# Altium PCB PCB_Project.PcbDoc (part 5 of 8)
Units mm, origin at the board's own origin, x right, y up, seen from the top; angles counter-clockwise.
Board outline 250 x 200 mm, 6 copper layers (Top Shielding/Sig, Sig 1, PWR, GND, Sig 4, Bottom Shielding/Sig), stack 1.568 mm thick; 736 components, 420 nets, 1929 pads, 2185 vias.
Unrouted connection lines stored in the file: 47.
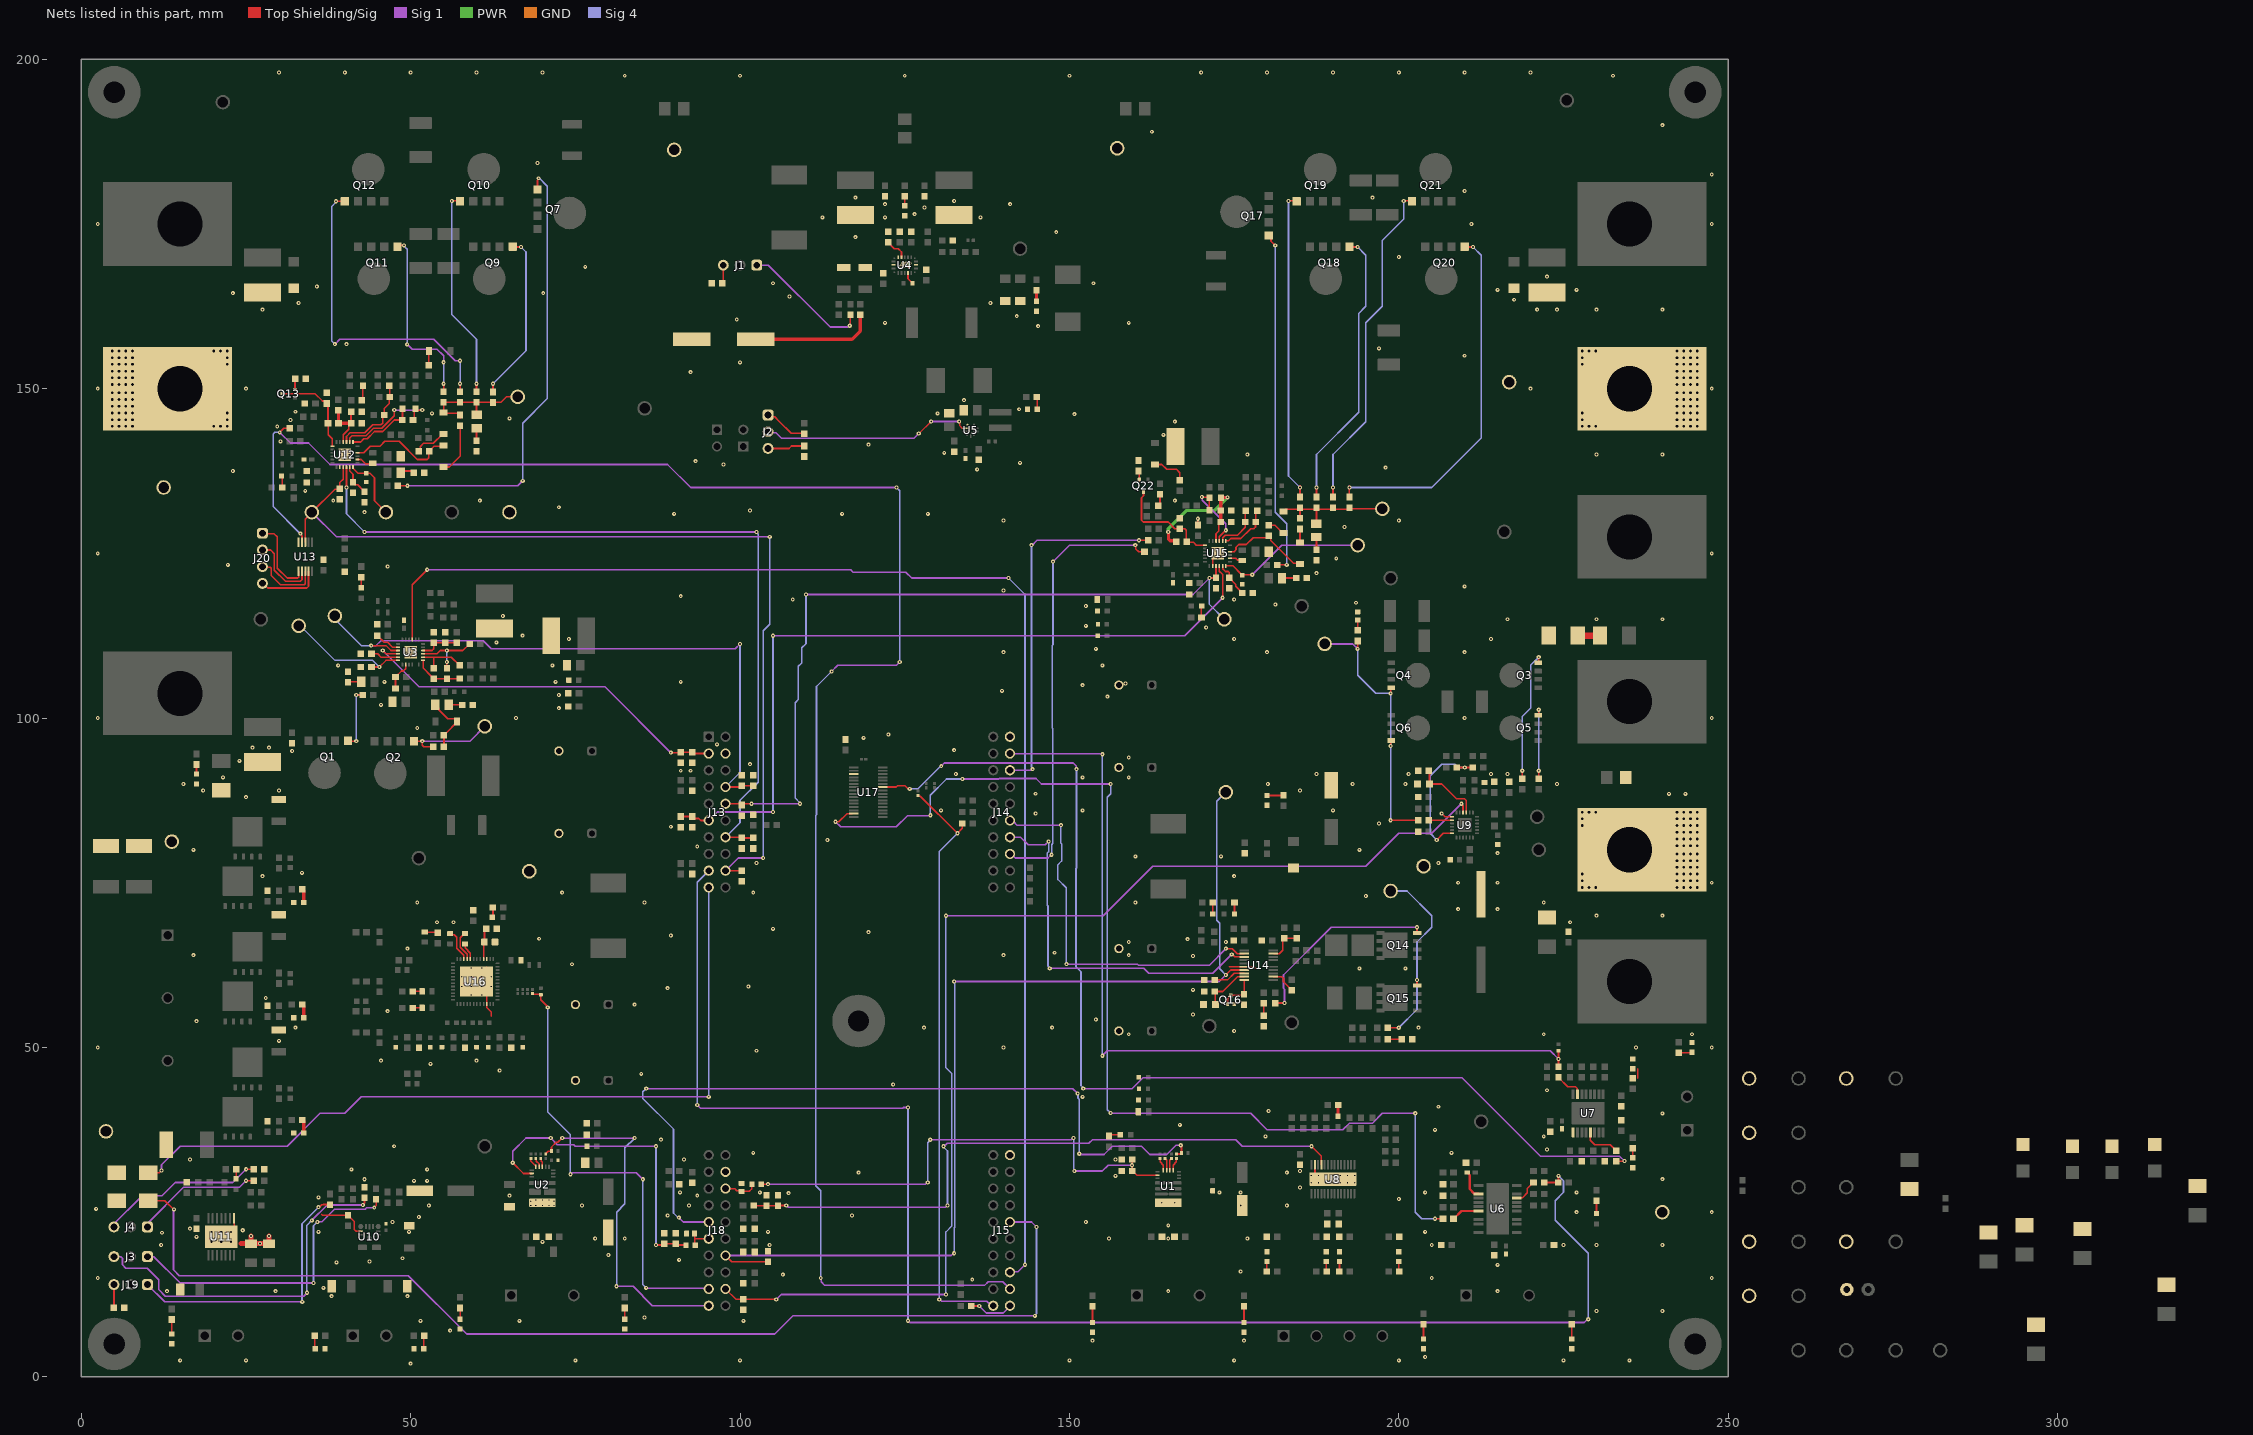
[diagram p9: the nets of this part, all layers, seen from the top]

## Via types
v1: diameter 0.635, hole 0.254, Top Shielding/Sig to Bottom Shielding/Sig, tented both sides, 778 vias
v2: diameter 0.6, hole 0.254, Top Shielding/Sig to Bottom Shielding/Sig, tented both sides, 726 vias
v3: diameter 0.813, hole 0.406, Top Shielding/Sig to Bottom Shielding/Sig, 522 vias
v4: diameter 0.5, hole 0.2, Top Shielding/Sig to Bottom Shielding/Sig, tented both sides, 95 vias
v5: diameter 0.5, hole 0.2, Top Shielding/Sig to Bottom Shielding/Sig, 39 vias
v6: diameter 0.635, hole 0.254, Top Shielding/Sig to Bottom Shielding/Sig, 10 vias
v7: diameter 0.63, hole 0.33, Top Shielding/Sig to Bottom Shielding/Sig, tented both sides, 6 vias
v8: diameter 0.75, hole 0.254, Top Shielding/Sig to Bottom Shielding/Sig, tented both sides, 6 vias
v9: diameter 0.5, hole 0.2, Top Shielding/Sig to Bottom Shielding/Sig, tented top, 3 vias

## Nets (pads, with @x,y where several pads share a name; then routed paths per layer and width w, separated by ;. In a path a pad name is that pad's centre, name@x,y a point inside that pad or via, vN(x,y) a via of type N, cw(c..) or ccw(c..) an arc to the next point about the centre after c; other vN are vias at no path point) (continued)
GND: C1.1 C2.1 C3.1 C4.1 C5.1 C6.2 C7.1 C8.1 C9.1 C10.1 C11.2 C12.2 C13.2 C14.2 C15.1 C16.1 C17.1 C18.1 C19.2 C20.2 C21.1 C23.2 C24.1 C25.2 C26.1 C27.1 C28.2 C29.2 C30.2 C31.2 C32.1 C33.1 C34.1 C35.2 C36.2 C37.1 C38.1 C40.1 C41.2 C42.2 C43.2 C44.2 C45.2 C46.2 C47.2 C49.1 C51.2 C54.2 C55.2 C56.2 C57.2 C58.2 C60.1 C61.1 C62.1 C63.1 C64.2 C65.2 C66.2 C67.2 C69.2 C70.2 C71.2 C72.2 C73.2 C74.2 C75.2 C76.2 C77.2 C78.2 C79.2 C80.2 C81.2 C82.2 C83.2 C84.2 C85.2 C86.2 C87.2 C88.2 C89.2 C90.2 C91.2 C92.2 C94.1 C95.2 C96.2 C97.1 C99.1 C100.1 C102.2 C103.2 C104.2 C105.2 C106.2 C107.2 C108.2 C109.2 C110.2 C111.2 C112.2 C114.1 C115.2 C116.1 C117.2 C118.2 C119.2 C120.2 C122.2 C123.2 C125.2 C127.2 C128.2 C129.1 C130.2 C131.2 C132.2 C133.2 C134.1 C135.2 C136.2 C137.1 C138.1 C140.2 C142.2 C144.1 C145.2 C146.2 C147.1 C148.2 C150.2 C151.2 C152.2 C153.2 C155.2 C157.2 C158.1 C159.2 C160.2 C161.2 C162.2 C163.1 C164.2 C167.2 C168.2 C170.2 C174.2 C178.2 C180.2 C185.2 C186.2 C187.2 C188.2 C189.1 C190.1 C191.1 C192.1 C196.1 C197.1 C198.1 C199.2 D1.2 D2.2 D4.2 D5.2 D6.2 D7.2 D11.2 D13.2 D15.2 D16.2 D17.2 D18.2 D20.2 D21.2 D22.2 D23.2 D26.1 D27.2 D29.2 D30.2 D31.2 D34.1 D35.2 D38.2 D39.1 D40.2 D44.1 D47.2 D48.2 D49.2 D55.2 D56.2 D57.2 D58.2 D59.2 D60.2 D61.2 D62.2 D63.2 D64.2 D65.2 J13.22 J14.20 J15.60 J18.62 Q16.2 R8.1 R14.1 R42.1 R43.1 R44.1 R45.1 R51.1 R54.1 R55.1 R56.1 R59.1 R60.1 R62.1 R73.1 R75.2 R81.2 R85.1 R102.1 R103.1 R119.1 R121.1 R126.1 R127.1 R128.2 R135.1 R137.1 R141.1 R145.1 R151.1 R152.1 R175.2 R188.1 R189.1 R190.1 R203.1 R207.2 R209.1 R211.1 R212.1 R236.2 R249.1 R250.1 R251.1 R252.1 R284.1 R285.1 R286.1 R287.2 R288.2 R289.2 R299.1 R303.1 R304.1 S1.1 S2.2 T5.1 T7.1 TP29.1 TP30.1 TP31.1 TP32.1 TP33.1 TP34.1 TP35.1 TP36.1 TP37.1 TP38.1 U1.7 U2.6 U3.8 U3.25 U4.6 U4.9 U4.19 U4.21 U5.4 U6.2 U7.1 U8.13 U8.29 U9.13 U10.11 U11.1 U11.15 U12.8 U12.25 U13.5 U14.6 U15.8 U15.25 U16.10 U16.27 U16.49 U17.3 | length 55
  Top Shielding/Sig w0.25: U11.15@21.25,21.25 21.625,21.25 23.2,22.825 U11.1@23.2,24.05 ; 36.5,24.65 36.6,24.55 38.75,24.55 R137.1@40.5,24.55 40.5,24.525 41.45,23.575 41.45,22.375 41.75,22.075 U10.11@42.4,22.075 ; C58.2@44.95,112.5 44.975,112.5 45.975,111.5 46.5,111.5 47.25,110.75 U3.8@48.1,110.75 ; U16.49@60,60 61.562,58.438 U16.10@61.562,56.6 61.562,56.063 62.25,55.375 62.25,54.75 ; v4(60.786,62.05) 61.437,62.05 U16.49@61.562,62.175 ; C147.1@169.5,129.3 v1(169.5,130.25) ; U15.8@171.75,123.1 171.75,124.95 v4(171.8,125) ; 174.25,62.25 U14.6@176.55,62.25 178,62.25 178.25,62 ; U8.13@187.25,32.2 187.266,32.184 187.266,30.875 188.141,30 U8.29@190,30 ; v1(206.5,85.5) 207,85 U9.13@208.1,85
  Top Shielding/Sig w0.35: C73.2@210.4,31 210.5,31 210.625,30.875 210.625,30.775 210.75,30.65 210.75,28.5 211.425,27.825 212.05,27.825 U6.2@212.1,27.775
  Top Shielding/Sig w0.75: 24.25,20.25 25.7,20.25 C109.2@25.75,20.2 ; v1(25.75,21.375) C109.2@25.75,20.2 ; v1(28.5,21.375) C110.2@28.5,20.2 28.45,20.25 v1(27.125,20.25) 25.8,20.25 C109.2@25.75,20.2
  GND w0.35: v3(7.761,152.667) 12.083,152.667 14.75,150 T5.1@15,150
  other v1: 24.5,22.25 43,30
  other v2: 50,2 15,2.5 25,2.5 75,2.5 100,2.5 150,2.5 175,2.5 200,2.5 225,2.5 235,2.5 204,3 153.5,5.5 176.5,5.5 56,7 51.5,8.5 66.5,8.5 100.5,8.5 85.5,9 230,10 240,10 38,12.25 49.5,12.25 13,13 29.5,13 165,13 215,13 36.75,13.5 135.25,14.75 2.5,15 205,15 247.5,15 106.5,15.5 176,16 215,17 38.75,17.375 43.75,17.5 90.75,17.75 48.75,18 80,18.5 12.125,20 104.5,20 205,20 225,20 230,20 240,20 70,20.5 78,21 82.5,21 156,21 165,21 177,21 17.5,21.25 12.254,21.871 36,22 49.75,22 104.25,22 204,22 16.5,22.5 165,23 47.25,23.5 152.5,23.5 51.25,24.25 89,24.5 117,24.5 227,25 247.5,25 2.25,25.5 52.75,26 76,26 92.25,26 176,26 183,26 200,27 36,27.25 65,27.5 93.5,27.5 107.375,27.875 90.875,28 103,28 172.75,28 176,28 204,28 227,28 185,28.75 50.5,29.75 52.5,29.75 240,30 157,30.5 118,31 183,31 185,31.25 41,31.5 52.5,31.5 16.5,33 91.5,33 157,33 102,34 208,34 222.5,34.5 47.5,35 88,36 179.75,36.5 222,36.5 205.5,37.5 166.75,38.25 240,40 180.25,40.362 206,41 152,42.5 222.5,43.5 123.25,44.375 85,46 63.5,46.5 53,47.5 45.5,48 60,48 102.5,49.5 2.5,50 140,50 236,50 247.5,50 30,51 159,52 222,52 244.5,52 175,52.5 32.5,53 127.923,53 147.375,53 203,53 17.5,54 154,54.25 168.75,55 46.5,55.5 84,56.5 28,57.5 168.75,58.75 89,59 101.25,59.25 194,62 201,62 74.5,62.625 168.75,63.875 17,64 140,64 159,64 147.75,64.375 49.5,65 159,66 173.75,66 167.942,66.442 69.5,66.5 89.5,67 119.5,67.5 105,68 54,69 56.5,69 226,69 230,70 240,70 209,71 215,71 51,72 85.5,72 160,72 222,72 195,73 73,73.5 102,73.5 209,75 215,75 247.5,75 27.5,76 175,76 33.5,76.5 102.5,78 206,78 160,79 173,79 215,79.5 17,80 194,80 93.5,80.5 113.25,81.5 89.5,83.5 197,84 144.875,85.5 130.5,86 152,86 190,86 25,88 144.875,88.509 18.5,89 30,89 185,89 15.5,90 180.125,90 193,90 201,90 224,90 21.5,91 152,91 159,91 132.75,91.5 187.5,91.5 201.5,91.5 214,91.5 216.5,91.5 91,92 92.5,92 101.5,93 24,93.5 159,94 32,95 132.5,95.125 26,95.5 28.5,95.5 96.5,96 118.766,96.996 122.5,97.5 51,98.5 2.5,100 66,100 210,100 247.5,100 72.5,101.5 45.5,102 155.75,103.25 72.5,103.5 139.75,104.125 152,105 158.5,105.25 46,105.5 72,105.5 91,105.5 39,108 71.5,108 155,108 140,110 180,110 210,110 154,110.5 63,111.5 74,112 175,112 214,112 67,112.5 170.75,113.75 152.5,114 216.5,115 230,115 240,115 64,115.5 152.5,117 181.25,117.25 193.5,117.5 108,118 175,118 91,118.5 140,119.375 210,120 187.5,122 46.5,123 22.25,123.25 190.5,124.25 2.5,125 247.5,125 191.75,129 140,130 200,130 90,131 115.5,131 128.5,131 43,131.25 101.5,131.5 72.5,132 38.25,133 60.5,133 166,133 34,134.5 23,137.5 136,137.75 198,138 97.5,138.5 142.5,138.75 93.25,139 177,140 230,140 240,140 131,140.25 119.5,141.5 30.25,142 164.25,143 29.75,144.25 166,145 31.75,145.25 65,145.5 150.75,146.125 53.25,146.25 130,146.25 32.5,146.5 142.375,146.875 134,148.25 2.5,150 25,150 220,150 247.5,150 92.5,152.5 100,154 210,155 197,156.125 40.25,156.75 145.25,159.5 122,160 159,160 99.5,160.5 142,161 27.5,162 221,162 224,162 230,162 240,162 33,163 138,163 217.5,163.5 107.5,164 23,164.5 70.125,164.5 215,165 227,165 35.75,165.5 105,166 153.625,166 222.5,167 76.5,168.5 200,170 117.5,173 148,173.75 2.5,175 211,175 247.5,175 112.5,176 122,176 136.5,176 126.5,176.5 128,177.5 122,178 141,178 132.5,178.5 117.5,179 196,179 210,180 247.5,182.5 69.25,184.25 162.5,189 240,190 82.5,197.5 100,197.5 125,197.5 150,197.5 232.5,197.5 30,198 40,198 50,198 60,198 70,198 170,198 180,198 190,198 200,198 210,198 220,198
  other v3: 4.713,144.285 5.729,144.285 6.745,144.285 7.761,144.285 20.112,144.285 21.128,144.285 22.144,144.285 227.856,144.285 228.872,144.285 229.888,144.285 242.239,144.285 243.255,144.285 244.271,144.285 245.287,144.285 4.713,145.301 5.729,145.301 6.745,145.301 7.761,145.301 22.144,145.301 227.856,145.301 242.239,145.301 243.255,145.301 244.271,145.301 245.287,145.301 4.713,146.317 5.729,146.317 6.745,146.317 7.761,146.317 22.144,146.317 227.856,146.317 242.239,146.317 243.255,146.317 244.271,146.317 245.287,146.317 4.713,147.333 5.729,147.333 6.745,147.333 7.761,147.333 242.239,147.333 243.255,147.333 244.271,147.333 245.287,147.333 4.713,148.349 5.729,148.349 6.745,148.349 7.761,148.349 242.239,148.349 243.255,148.349 244.271,148.349 245.287,148.349 4.713,149.365 5.729,149.365 6.745,149.365 7.761,149.365 242.239,149.365 243.255,149.365 244.271,149.365 245.287,149.365 4.713,150.635 5.729,150.635 6.745,150.635 7.761,150.635 242.239,150.635 243.255,150.635 244.271,150.635 245.287,150.635 4.713,151.651 5.729,151.651 6.745,151.651 7.761,151.651 242.239,151.651 243.255,151.651 244.271,151.651 245.287,151.651 4.713,152.667 5.729,152.667 6.745,152.667 242.239,152.667 243.255,152.667 244.271,152.667 245.287,152.667 4.713,153.683 5.729,153.683 6.745,153.683 7.761,153.683 22.144,153.683 227.856,153.683 242.239,153.683 243.255,153.683 244.271,153.683 245.287,153.683 4.713,154.699 5.729,154.699 6.745,154.699 7.761,154.699 22.144,154.699 227.856,154.699 242.239,154.699 243.255,154.699 244.271,154.699 245.287,154.699 4.713,155.715 5.729,155.715 6.745,155.715 7.761,155.715 20.112,155.715 21.128,155.715 22.144,155.715 227.856,155.715 228.872,155.715 229.888,155.715 242.239,155.715 243.255,155.715 244.271,155.715 245.287,155.715
  other v4: 68.25,26 69,26 70,26 71,26 71.75,26 68.25,26.65 71.75,26.65 69,26.85 70,26.85 71,26.85 186.7,29.45 187.8,29.45 188.9,29.45 190,29.45 191.1,29.45 192.2,29.45 193.3,29.45 186.7,30.55 187.8,30.55 188.9,30.55 190,30.55 191.1,30.55 192.2,30.55 193.3,30.55 59.214,57.95 60.786,57.95 57.764,59.26 59.214,59.26 60.786,59.26 62.236,59.26 57.764,60.74 59.214,60.74 60.786,60.74 62.236,60.74 59.214,62.05 50,109.3 49.3,110 50,110 50.7,110 50,110.7 172.5,124.3 172.5,125 173.2,125 172.5,125.7 40,139.3 39.3,140 40,140 40.7,140 40,140.7
  other v5: 164,26.425 166,26.425 124.415,168.6 124.965,168.6 125.515,168.6 124.69,169.05 125.24,169.05 125.79,169.05
  other v7: 19.75,20.5 21.25,20.5 22.75,20.5 19.75,22 21.25,22 22.75,22
HGATE_74900_11: R117.1 U9.14 | length 3.5
  Top Shielding/Sig w0.25: R117.1@204.55,84.5 U9.14@208.1,84.5
I2t_TPS1212_input1_2: C129.2 TP17.1 U12.12 | length 10
  Top Shielding/Sig w0.25: U12.12@41.25,138.1 41.25,137.925 42,137.175 C129.2@43.25,137.175 43.254,137.171 43.829,137.171 44.5,136.5 44.5,133 TP17.1@46.25,131.25
I2t_TPS1212_input2_3: C158.2 TP27.1 U15.12 | length 22.5
  Top Shielding/Sig w0.25: U15.12@173.75,123.1 174.825,123.1 176.025,121.9 176.025,121.875 176.225,121.675 C158.2@176.25,121.675 176.325,121.75 v1(177.75,121.75)
  Sig 1 w0.25: v1(177.75,121.75) 182.25,126.25 TP27.1@193.75,126.25
I2t_TPS1214_7: C55.1 TP6.1 U3.12 | length 19.3
  Top Shielding/Sig w0.25: C55.1@44,107.75 v1(45.25,107.75) 46.25,108.75 U3.12@48.1,108.75 ; C55.1@44,107.8 C55.1@44.025,107.775
  Sig 4 w0.25: TP6.1@33.125,114.125 38.5,108.75 44.25,108.75 v1(45.25,107.75)
IDIR_TPS1212_input1_1: J15.51 R181.1 | length 6.8
  Top Shielding/Sig w0.25: R181.1@135.1,10.75 v1(136.3,10.75)
  Sig 1 w0.25: v1(136.3,10.75) 137.355,9.695 139.945,9.695 J15.51@141,10.75
IDIR_TPS1212_input2_1: J14.13 R242.1 | length 67
  Top Shielding/Sig w0.25: v1(160,126.25) 160.074,126.176 160.074,125.676 160.5,125.25 R242.1@161.25,125.25
  Sig 1 w0.25: J14.13@140.97,79.375 141.139,79.375 141.764,78.75 146.75,78.75 147.25,79.25 v1(147.292,79.25) ; v1(147.5,123.75) 150,126.25 v1(160,126.25)
  Sig 4 w0.25: v1(147.292,79.25) 147.292,80.791 147.485,80.984 147.485,98.381 147.375,98.491 147.375,111.006 147.5,111.131 v1(147.5,123.75)
IMON_LM74900_1: J18.69 R126.2 U9.10 | length 179.4
  Top Shielding/Sig w0.25: J18.69@97.79,13.335 99.325,11.8 R126.2@100.5,11.8 100.55,11.75 v1(105.5,11.75) ; v1(209.5,87) 209.75,86.75 U9.10@209.75,85.65
  Sig 1 w0.25: v1(105.5,11.75) 106.25,12.5 v1(131.25,12.5) ; v1(131.25,70) 155.146,70 162.646,77.5 195,77.5 200,82.5 205,82.5 v1(209.5,87)
  Sig 4 w0.25: v1(131.25,12.5) 131.25,21.993 132.143,22.886 132.143,46.031 131.25,46.923 v1(131.25,70)
IMON_TPS1211_1: J18.67 R211.2 TP22.1 U14.7 | length 156.6
  Top Shielding/Sig w0.25: J18.67@97.79,18.415 98.755,17.45 R211.2@104.25,17.45 ; v2(173.75,61) 174.5,61.75 U14.7@176.55,61.75
  Sig 1 w0.25: J18.67@97.79,18.415 132.061,18.415 132.396,18.75 v1(132.5,18.75) ; v1(132.5,60) 172.75,60 v2(173.75,61)
  Sig 4 w0.25: v1(132.5,18.75) 132.5,22.607 132.593,22.7 132.593,59.803 132.5,59.896 v1(132.5,60) ; TP22.1@173.5,88.75 173.5,88.5 172.375,87.375 172.375,69.284 172.812,68.846 172.812,61.938 v2(173.75,61)
IMON_TPS1212_input1: C132.1 J13.29 R299.2 TP18.1 U12.9 U13.3 | length 143.4
  Top Shielding/Sig w0.25: U13.3@34,126.7 34,130.157 35,131.157 TP18.1@35,131.25 38.5,134.75 39.25,134.75 R299.2@39.25,134.8 39.25,135.75 39.75,136.25 U12.9@39.75,138.1 ; J13.29@97.79,76.835 100.215,76.835 C132.1@100.25,76.8
  Sig 1 w0.25: TP18.1@35,131.25 38.75,127.5 v1(104.5,127.5) ; J13.29@97.79,76.835 99.705,78.75 v2(103.5,78.75)
  Sig 4 w0.25: v2(103.5,78.75) 103.5,113.25 104.5,114.25 v1(104.5,127.5)
IMON_TPS1212_input2: C161.1 J13.25 R252.2 TP28.1 U15.9 | length 116.5
  Top Shielding/Sig w0.25: J13.25@97.79,86.995 100.055,86.995 C161.1@100.25,86.8 100.45,87 v1(101.75,87) ; v1(171.25,121.25) 172.2,121.25 R252.2@172.25,121.3 U15.9@172.25,123.1
  Sig 1 w0.25: v1(101.75,87) v1(109.107,87) ; v1(110,118.75) 168.75,118.75 v1(171.25,121.25)
  Sig 4 w0.25: v1(109.107,87) 109.107,87.104 108.357,87.854 108.357,102.315 108.85,102.807 108.85,107.844 109.35,108.344 109.35,110.651 110,111.301 v1(110,118.75) ; v1(171.25,121.25) 171.25,117.25 TP28.1@173.5,115
IMON_TPS1214_1: C57.1 J13.24 R45.2 TP7.1 U3.9 | length 95.6
  Top Shielding/Sig w0.25: v1(44,111) 46.25,111 47,110.25 U3.9@48.1,110.25 ; J13.24@97.79,89.535 100.085,89.535 R45.2@100.25,89.7 C57.1@102,89.7
  Sig 1 w0.25: v1(44,111) 44.75,111 45.5,111.75 61,111.75 62.25,110.5 99.25,110.5 v1(100,111.25)
  Sig 4 w0.25: TP7.1@38.528,114.972 42.5,111 v1(44,111) ; J13.24@97.79,89.535 100,91.745 v1(100,111.25)
INP_G_TPS1211_1: J14.15 U14.2 | length 58.3
  Top Shielding/Sig w0.2: v1(173.75,65) 174.75,65 175.5,64.25 U14.2@176.55,64.25
  Sig 1 w0.25: J14.15@141,84.25 141.527,84.25 142.027,83.75 v1(148.708,83.75) ; v1(149.546,62.643) 160.329,62.643 160.521,62.45 171.2,62.45 v1(173.75,65)
  Sig 4 w0.25: v1(148.708,83.75) 148.708,81.027 148.808,80.927 148.808,78.308 148.25,77.75 148.25,75.5 149.5,74.25 149.5,62.688 v1(149.546,62.643)
INP_TPS1211_1: J14.14 U14.3 | length 57.2
  Top Shielding/Sig w0.25: v1(174.625,64.125) 174.729,64.125 175.104,63.75 U14.3@176.55,63.75
  Sig 1 w0.25: J14.14@140.97,81.915 142.585,81.915 143.75,80.75 146.143,80.75 146.164,80.772 146.341,80.772 146.819,81.25 v1(146.843,81.25) ; v1(147,62) 161.302,62 162.052,61.25 171.75,61.25 v1(174.625,64.125)
  Sig 4 w0.25: v1(146.843,81.25) 146.843,79.709 146.65,79.516 146.65,71.6 146.75,71.5 146.75,62.339 147,62.089 v1(147,62)
INP_TPS1212_input1_1: J15.52 R176.1 U13.4 | length 279.4
  Top Shielding/Sig w0.25: v2(30.123,143.374) 30.749,144 R176.1@31.65,144 R176.1@31.75,144 ; v2(33.25,128) 33.25,127.942 33.5,127.692 U13.4@33.5,126.7
  Sig 1 w0.25: v2@30.25,143.25 31.75,141.75 34.5,141.75 37.75,138.5 89,138.5 92.5,135 v1(123.75,135) ; v2(112.25,15) 112.317,14.933 112.317,14.433 112.875,13.875 137.1,13.875 137.66,14.435 139.87,14.435 J15.52@140.97,13.335 141,13.305 J15.52@141,13.25 ; v1(113.895,107.069) 114.826,108 123.75,108 v1(124.25,108.5)
  Sig 4 w0.25: v2(30.123,143.374) 29.374,143.374 29.125,143.125 29.125,132.125 v2(33.25,128) ; v2(112.25,15) 112.25,28.25 111.5,29 111.5,85.204 111.607,85.312 111.607,104.782 v1(113.895,107.069) ; v1(123.75,135) 124.25,134.5 v1(124.25,108.5)
INP_TPS1212_input2_1: J14.18 R237.1 | length 55.5
  Top Shielding/Sig w0.25: v1(160.55,127) R237.1@161.8,127
  Sig 1 w0.25: J14.18@141,92 141.075,92.075 144.23,92.075 144.405,92.25 v2(144.425,92.25) ; v1(144.25,126.25) 144.339,126.25 145.089,127 v1@160.565,127
  Sig 4 w0.25: v1(144.25,126.25) 144.25,92.52 144.425,92.345 v2(144.425,92.25)
INP_TPS1214_1: J15.53 U3.3 | length 208.3
  Top Shielding/Sig w0.25: U3.3@50.25,111.9 50.25,120.25 v1(52.5,122.5)
  Sig 1 w0.25: v1(52.5,122.5) 116.793,122.5 117.15,122.143 125.159,122.143 126.051,121.25 v1(140.75,121.25) ; J15.53@141,16 141.026,15.974 142.224,15.974 v1(143.25,17)
  Sig 4 w0.25: v1(140.75,121.25) 143.25,118.75 v1(143.25,17)
IOC_TPS1212_input1_2: C131.1 R189.2 U12.11 | length 4.9
  Top Shielding/Sig w0.25: U12.11@40.75,138.1 40.75,137.5 41.25,137 R189.2@41.25,135.8 ; R189.2@41.25,135.75 41.575,135.425 41.95,135.425 43,134.375 C131.1@43,134.35
IOC_TPS1212_input2_3: C160.1 R250.2 U15.11 | length 5.6
  Top Shielding/Sig w0.25: U15.11@173.25,123.1 173.25,122.686 173.686,122.25 174.104,122.25 174.25,122.104 174.25,121.5 174.25,121.275 175.238,120.288 175.238,119.987 176.225,119 C160.1@176.25,119
IOC_TPS1214_7: R43.2 U3.11 | length 4.3
  Top Shielding/Sig w0.25: R43.2@44.05,109.75 45,109.75 45.5,109.25 U3.11@48.1,109.25
IPROPI_DRV8245_1: C6.1 J18.63 R5.2 | length 5.1
  Top Shielding/Sig w0.25: J18.63@97.79,28.575 99.175,28.575 99.5,28.25 100.15,28.25 C6.1@100.25,28.15 101.4,28.15 101.75,28.5 101.75,29.2 R5.2@101.8,29.25
IPROPI_DRV8263_1: C25.1 J18.46 R12.2 | length 4
  Top Shielding/Sig w0.25: C25.1@93.1,21.75 93.1,21 ; R12.2@93.2,20 93.1,20.1 93.1,21 ; J18.46@95.25,20.955 93.145,20.955 93.1,21
ISCP-_TPS1214_7: C50.2 R36.1 U3.21 | length 10.4
  Top Shielding/Sig w0.25: U3.21@51.9,109.75 54,109.75 54.5,110.25 v1(55.5,110.25) 57.925,110.25 58.925,111.25 R36.1@58.95,111.25 ; C50.2@55.5,107.55 v1(55.5,108.5)
  Sig 4 w0.25: v1(55.5,108.5) v1(55.5,110.25)
ISCP_TPS1211_8: C139.1 R213.2 U14.19 | length 5.4
  Top Shielding/Sig w0.2: U14.19@181,64.25 181.875,64.25 182.375,64.75 182.375,66.325 C139.1@182.625,66.575 R213.2@184.5,66.575
ITMPO_TPS1212_input1: C130.1 J13.27 R188.2 U12.10 | length 123.2
  Top Shielding/Sig w0.25: v1(40.25,135) 40.25,136.551 U12.10@40.25,138.1 ; J13.27@97.79,81.915 100.135,81.915 C130.1@100.25,81.8 R188.2@102,81.8
  Sig 1 w0.25: v1(43,128.25) v1(102.5,128.25)
  Sig 4 w0.25: v1(40.25,135) 40.25,131 v1(43,128.25) ; J13.27@97.79,81.915 100,84.125 100,87.5 102.75,90.25 102.75,127.911 102.5,128.161 v1(102.5,128.25)
ITMPO_TPS1212_input2: C159.1 J13.6 R249.2 U15.10 | length 117.2
  Top Shielding/Sig w0.25: C159.1@91,85.05 R249.2@92.75,85.05 93.05,84.75 93.75,84.75 94.045,84.455 J13.6@95.25,84.455 ; U15.10@172.75,123.1 172.75,122.293 173.25,121.793 v1(173.25,118.25)
  Sig 1 w0.25: J13.6@95.25,84.455 96.545,85.75 v1(105,85.75) ; v1(105,112.5) 167.5,112.5 v1(173.25,118.25)
  Sig 4 w0.25: v1(105,85.75) v1(105,112.5)
ITMPO_TPS1214_1: C56.1 J13.2 R42.2 U3.10 | length 58.6
  Top Shielding/Sig w0.25: v1(45.75,110.25) 46.25,109.75 U3.10@48.1,109.75 ; v1(89.5,94.75) 90.95,94.75 R42.2@91,94.8 C56.1@92.75,94.8 92.935,94.615 J13.2@95.25,94.615
  Sig 1 w0.25: v1(45.75,110.25) 51.25,104.75 79.5,104.75 v1(89.5,94.75)
IWRN_TPS1211_8: R212.2 U14.8 | length 4.9
  Top Shielding/Sig w0.25: R212.2@172.05,60.25 174,60.25 175,61.25 U14.8@176.55,61.25
LHI_HCS05_4: R74.1 U6.6 | length 4.3
  Top Shielding/Sig w0.35: R74.1@208.3,24 208.325,24 209.5,25.175 U6.6@212.1,25.175
LHI_HCS010_4: R80.1 U7.5 | length 5.8
  Top Shielding/Sig w0.25: U7.5@229.075,37.1 229.075,35.925 229.75,35.25 232.075,35.25 233,34.325 R80.1@233,34.3
LHI_TPS2HCS05_1: R74.2 U17.15 | length 168.6
  Top Shielding/Sig w0.25: v1(114.5,84.25) 115,84.25 116.25,85.5 U17.15@117,85.5 ; v1(205.5,24) R74.2@206.7,24
  Sig 1 w0.25: v1(114.5,84.25) 115.273,83.477 123.727,83.477 125.408,85.158 128.453,85.158 128.471,85.176 128.819,85.176 v1(128.893,85.25) ; v2(133.75,90.75) 139.262,90.75 139.337,90.825 144.925,90.825 145.75,90 v1(156.25,90) ; v1(156.25,40.042) 156.292,40 177.5,40 180,37.5 191.5,37.5 192.5,38.5 196,38.5 197.5,40 v1(202.5,40)
  Sig 4 w0.25: v1(128.893,85.25) 128.893,88.301 131.341,90.75 v2(133.75,90.75) ; v1(156.25,40.042) 155.75,40.542 155.75,50.658 155.75,63.158 155.75,88 156.25,88.5 v1(156.25,90) ; v1(202.5,40) 202.5,25 203.5,24 v1(205.5,24)
LHI_TPS2HCS10_1: R80.2 U17.26 | length 170.3
  Top Shielding/Sig w0.25: U17.26@121.65,89.5 121.675,89.525 123.7,89.525 123.925,89.75 125,89.75 125.426,89.324 125.676,89.324 v1(125.75,89.25) ; R80.2@233,32.7 233.05,32.75 v1(234.25,32.75)
  Sig 1 w0.25: v2(130.543,92.7) 131.019,93.175 150.575,93.175 151.008,92.742 151.008,92.317 v2(151.075,92.25) ; v1(152.107,43.75) 159.5,43.75 161.125,45.375 209.625,45.375 221.5,33.5 233.5,33.5 v1(234.25,32.75)
  Sig 4 w0.25: v1(125.75,89.25) 127,89.25 v2@130.5,92.75 ; v2(151.075,92.25) 151.075,77.24 151,77.165 151,62.25 151.75,61.5 151.75,44.212 152.107,43.854 v1(152.107,43.75)
MODE_14: R51.2 U4.5 | length 3.4
  Top Shielding/Sig w0.25: R51.2@122.5,172.2 122.5,172.175 123.425,171.25 124,171.25 124.5,170.75 U4.5@124.5,169.95
nCS_DRV8245_1: J18.45 R6.2 R9.1 | length 120.6
  Top Shielding/Sig w0.25: R9.1@166.25,33.83 166.875,33.83 R6.2@167,33.955 ; R6.2@167,34 v1@167,35
  Sig 1 w0.25: v1(85.75,43.75) 150.5,43.75 v2(151.25,43) ; v2(90.707,24.151) 91.358,23.5 J18.45@95.25,23.5 ; v1(151.5,33.857) 151.574,33.784 151.716,33.784 151.75,33.75 155.25,33.75 156.5,35 160.95,35 162.2,33.75 164.75,33.75 166.166,35.166 v1(166.884,35.166)
  Sig 4 w0.25: v1(85.75,43.75) 85.25,43.25 85.25,42.25 89.892,37.607 89.892,24.857 v2@90.5,24.25 ; v2(151.25,43) 151.291,42.959 151.291,42.325 151.5,42.116 v1(151.5,33.857)
nCS_DRV8263_1: J18.50 R18.2 R20.1 | length 53.6
  Top Shielding/Sig w0.25: R20.1@70.5,33.83 70.5,33.85 70.9,34.25 R18.2@71.25,34.25 ; R18.2@71.375,34.25 71.375,34.875 72.088,35.588 72.338,35.588 v1(73,36.25)
  Sig 1 w0.2: v1(73,36.25) v1(84,36.25) ; v1(81.25,13.75) 83.75,13.75 86.705,10.795 J18.50@95.25,10.795
  Sig 4 w0.2: v1(81.25,13.75) 81.25,25 82.5,26.25 82.5,34.75 v1(84,36.25)
nCS_DRV8363_1: J18.49 R257.2 R260.1 | length 68
  Top Shielding/Sig w0.25: R260.1@68.5,58.17 68.5,58.15 68.585,58.065 69.685,58.065 R257.2@69.75,58 69.75,57.25 v1@70.75,56.25
  Sig 1 w0.25: v1(74.25,30.75) 74.339,30.75 74.589,31 84.25,31 v1(85.25,30) ; v2(85.75,13.5) 85.817,13.433 95.183,13.433 J18.49@95.25,13.5
  Sig 4 w0.25: v1(70.804,56.086) 70.804,40.196 74.25,36.75 v1(74.25,30.75) ; v1(85.25,30) 85.25,14 v2(85.75,13.5)
nCS_HCS05_4: R72.2 U6.16 | length 3.9
  Top Shielding/Sig w0.25: U6.16@217.9,27.125 217.959,27.184 218.773,27.184 219.508,27.919 219.508,28.583 220.425,29.5 R72.2@220.45,29.5
nCS_HCS10_4: R89.2 U7.15 | length 4.4
  Top Shielding/Sig w0.25: R89.2@224.25,45.45 224.25,45.425 225.659,44.016 226.823,44.016 227.066,43.773 227.066,42.959 U7.15@227.125,42.9
nCS_TPS2HCS05_1: J13.9 R66.1 R72.1 | length 232.3
  Top Shielding/Sig w0.25: R72.1@222.05,29.5 R66.1@224.2,29.5 224.25,29.55 v1(224.25,30.5)
  Sig 1 w0.25: v1(93.5,41.25) 94,40.75 124.682,40.75 124.808,40.875 125.483,40.875 v1(125.5,40.893) ; v1(125.5,8.5) 125.75,8.25 228.161,8.25 228.661,8.75 v1(228.75,8.75)
  Sig 4 w0.25: v1(93.5,41.25) 93.5,75.085 J13.9@95.25,76.835 ; v1(125.5,8.5) v1(125.5,40.893) ; v1(224.25,30.5) 225,29.75 225,28 223.75,26.75 223.75,23.75 228.75,18.75 v1(228.75,8.75)
nCS_TPS2HCS10_1: J14.19 R88.2 R89.1 | length 132.4
  Top Shielding/Sig w0.25: R89.1@224.25,47.05 v1(224.25,48.25) R88.2@224.25,49.5
  Sig 1 w0.25: J14.19@140.97,94.615 141.028,94.557 154.943,94.557 v1(155,94.5) ; v1(155,48.75) 155.75,49.5 223,49.5 v1(224.25,48.25)
  Sig 4 w0.25: v1(155,48.75) v1(155,94.5)
nCS_TXE8124_1: J15.71 R291.2 R296.1 | length 90.7
  Top Shielding/Sig w0.25: R296.1@127,88.25 127,88.23 127.085,88.145 127.355,88.145 v1(133,82.5) 133.75,83.25 133.75,83.95 R291.2@133.7,84
  Sig 1 w0.25: v1(130.25,11.75) 130.288,11.75 130.589,11.449 137.435,11.449 138.089,10.795 J15.71@138.43,10.795
  Sig 4 w0.25: v1(130.25,11.75) 130.25,79.75 v1(133,82.5)
NetC5_2: C5.2 R5.1 R8.2 U1.2 | length 73.9
  Top Shielding/Sig w0.25: R5.1@103.2,29.25 v1(104.25,29.25) ; R8.2@159.55,33 C5.2@159.55,31.25 159.575,31.25 160.2,30.625 U1.2@163.375,30.625
  Sig 1 w0.25: v1(104.25,29.25) 128.146,29.25 128.396,29.5 v1(128.5,29.5) ; v1(128.857,36) 150.253,36 150.503,36.25 v1(150.607,36.25) ; v1(150.75,31.25) 155,31.25 155.875,32.125 v1(159.5,32.125)
  Sig 4 w0.25: v1(128.5,29.5) 128.5,35.538 128.857,35.896 v1(128.857,36) ; v1(150.607,36.25) 150.679,36.179 150.679,31.321 v1(150.75,31.25)
NetC26_2: C26.2 R12.1 R14.2 U2.2 | length 48.1
  Top Shielding/Sig w0.25: v1(65.5,32.5) 67.125,30.875 U2.2@68.375,30.875 ; v1(87.25,20) 88.3,20 C26.2@88.5,20.2 ; C26.2@88.5,20.2 R14.2@90.25,20.2 90.45,20 R12.1@91.8,20
  Sig 1 w0.25: v1(65.5,32.5) 65.5,34.25 67.5,36.25 v1(71.25,36.25) 72.25,35.25 74.75,35.25 75,35 v1(87.25,35)
  Sig 4 w0.25: v1(87.25,20) v1(87.25,35)
NetC40_2: C40.2 R25.1 | length 2
  Top Shielding/Sig w0.25: C40.2@40.5,105.45 40.55,105.5 R25.1@42.484,105.5
NetC44_1: C44.1 C45.1 R27.1 TP40.1 U3.22 | length 6.2
  Top Shielding/Sig w0.25: U3.22@51.9,110.25 53.25,110.25 53.5,110.5 C45.1@53.5,111.45 C44.1@55.25,111.45 R27.1@57,111.45
NetC48_1: C48.1 C50.1 R32.1 U3.19 | length 7.4
  Top Shielding/Sig w0.25: U3.19@51.9,108.75 51.9,107.6 52.5,107 52.5,106.975 53.5,105.975 C48.1@53.5,105.95 C50.1@55.5,105.95 57.4,105.95 R32.1@57.45,106
NetC48_2: C48.2 R31.1 U3.20 | length 7.8
  Top Shielding/Sig w0.25: U3.20@51.9,109.25 53.5,109.25 ; C48.2@53.5,107.55 53.5,109.25 ; R31.1@57.45,108 57.425,108 56.175,109.25 53.5,109.25
NetC49_2: C49.2 R34.1 | length 2.1
  Top Shielding/Sig w0.25: R34.1@55.766,102 C49.2@57.825,102
NetC52_2: C52.2 C53.2 TP56.1 U3.14 | length 4.4
  Top Shielding/Sig w0.25: C52.2@47.7,104.5 C53.2@47.7,106.25 47.725,106.25 48.618,107.143 48.893,107.143 49.25,107.5 U3.14@49.25,108.1
NetC59_2: C59.2 U4.15 | length 1.8
  Top Shielding/Sig w0.25: U4.15@125.5,167.55 125.5,166.7 126.175,166.025 C59.2@126.175,166
NetC67_1: C67.1 R46.1 | length 18.7
  Top Shielding/Sig w0.5: C67.1@102.625,157.375 C67.1@102.75,157.5 ; C67.1@102.75,157.25 103,157.5 117,157.5 118.25,158.75 R46.1@118.25,161.2
NetC92_1: C92.1 R101.1 R103.2 U8.11 | length 99.1
  Top Shielding/Sig w0.25: R101.1@102.05,26 102.1,25.95 R103.2@104,25.95 C92.1@105.75,25.95 105.8,26 v1(107,26) ; v1(186.75,35) 188.25,33.5 U8.11@188.25,32.2
  Sig 1 w0.25: v1(107,26) 107.089,26 107.339,25.75 131.161,25.75 131.411,26 v1(131.5,26) ; v1(130.893,35) 130.997,35 131.431,35.434 152.934,35.434 153.5,36 175.25,36 176.25,35 v1(186.75,35)
  Sig 4 w0.25: v1(130.893,35) 130.893,34.896 131.5,34.288 v1(131.5,26)
NetC97_2: C97.2 R113.2 | length 1.6
  Top Shielding/Sig w0.25: R113.2@193.75,113.3 C97.2@193.75,114.873
NetC101_1: C101.1 R118.1 U9.18 | length 21.5
  Top Shielding/Sig w0.25: v1(205.75,81.5) 206.75,82.5 U9.18@208.1,82.5 ; C101.1@208.8,92.5 v1(210,92.5) R118.1@211.2,92.5
  Sig 4 w0.25: v1(205.75,81.5) 204.75,82.5 204.75,91.25 206.5,93 208.5,93 209,92.5 v1(210,92.5)
NetC102_1: C102.1 R128.1 U9.9 | length 10.5
  Top Shielding/Sig w0.25: C102.1@204.55,92 204.651,91.899 R128.1@204.651,90 206.5,90 208.75,87.75 209.98,87.75 210.25,87.48 U9.9@210.25,85.65
NetC113_2: C113.2 R154.1 | length 2.1
  Top Shielding/Sig w0.25: C113.2@42.6,148.25 42.75,148.4 R154.1@42.75,150.25
NetC114_2: C114.2 R158.1 | length 1.9
  Top Shielding/Sig w0.25: R158.1@48.516,137.5 C114.2@50.45,137.5
NetC119_1: C119.1 C120.1 R166.1 R172.2 TP48.1 U12.22 | length 9
  Top Shielding/Sig w0.25: R166.1@39,146.7 R166.1@39.05,146.65 ; C119.1@40.95,144.75 C120.1@40.95,146.5
  Top Shielding/Sig w0.254: U12.22@39.75,141.9 39.75,143 40.577,143.827 40.577,144.402 40.925,144.75 C119.1@40.95,144.75
  Top Shielding/Sig w0.5: R166.1@39.05,146.65 R172.2@39.05,144.75 C119.1@40.925,144.75
NetC121_1: C121.1 R168.1 U12.19 | length 10.6
  Top Shielding/Sig w0.25: U12.19@41.25,141.9 42.4,141.9 42.9,142.4 43.4,142.4 44.5,143.5 45.75,143.5 47.5,145.25 C121.1@48.75,145.25 R168.1@48.75,146.95
NetC121_2: C121.2 R167.1 U12.20 | length 16.7
  Top Shielding/Sig w0.25: U12.20@40.75,141.9 40.75,142.5 41.1,142.85 43.214,142.85 44.364,144 45.614,144 47.5,145.886 v1(47.5,146.75) ; C121.2@50.55,145.25 50.55,146.75 R167.1@50.75,146.95 50.95,146.75 v1(51.75,146.75)
  Sig 1 w0.25: v1(47.5,146.75) v1(51.75,146.75)
NetC122_1: C122.1 R174.1 | length 1.9
  Top Shielding/Sig w0.25: C122.1@60,142.1 R174.1@60,144
NetC123_1: C123.1 Q13.3 R172.1 U12.1 | length 14.2
  Top Shielding/Sig w0.25: Q13.3@30.55,149.25 35.485,149.25 36.615,148.12 36.9,148.12 37.25,147.77 C123.1@37.25,147.75 37.45,147.55 R172.1@37.45,144.75 37.5,144.7 37.5,143 38.1,142.4 U12.1@38.1,141.25
NetC124_2: C124.2 R177.1 R305.1 U12.21 | length 12.8
  Top Shielding/Sig w0.25: U12.21@40.25,141.9 40.25,142.75 40.8,143.3 43.027,143.3 44.227,144.5 45.477,144.5 45.75,144.773 45.75,145.75 C124.2@46,146 46,147 46.75,147.75 R305.1@46.75,148.5 ; R177.1@46.75,150.25 46.8,150.2 R305.1@46.8,148.75
NetC126_1: C126.1 TP52.1 U12.14 | length 2.7
  Top Shielding/Sig w0.25: U12.14@41.9,139.25 42.5,139.25 43.146,138.604 44.104,138.604 C126.1@44.25,138.75
NetC134_2: C134.2 R194.2 | length 1.9
  Top Shielding/Sig w0.25: C134.2@179.5,54.8 R194.2@179.5,56.7
NetC140_1: C140.1 R204.1 | length 2.1
  Top Shielding/Sig w0.25: R204.1@198.3,51.25 C140.1@200.45,51.25
NetC141_2: C141.2 TP58.1 U14.12 | length 4
  Top Shielding/Sig w0.25: U14.12@180.95,60.75 182.25,60.75 182.5,60.5 182.5,59.975 183.75,58.725 C141.2@183.75,58.7
NetC142_1: C142.1 R207.1 U14.9 | length 7.5
  Top Shielding/Sig w0.25: R207.1@172.151,56.5 172.151,58.399 C142.1@172.05,58.5 173.25,58.5 175.5,60.75 U14.9@176.55,60.75
NetC143_2: C143.2 R217.1 | length 1.9
  Top Shielding/Sig w0.25: C143.2@163.75,132.1 R217.1@163.75,133.95
NetC144_2: C144.2 R221.1 | length 2.2
  Top Shielding/Sig w0.25: R221.1@182.266,121.25 C144.2@184.45,121.25
NetC149_1: C149.1 R229.1 U15.19 | length 7.9
  Top Shielding/Sig w0.25: U15.19@173.75,126.9 174.15,126.9 174.5,127.25 176,127.25 177.5,128.75 178,128.75 178.25,129 C149.1@178.25,129.75 ; C149.1@178.275,129.725 C149.1@178.3,129.75 178.3,131.25 R229.1@178.5,131.45
NetC149_2: C149.2 R228.1 U15.20 | length 7.1
  Top Shielding/Sig w0.25: U15.20@173.25,126.9 173.25,127.364 173.636,127.75 175.5,127.75 176.7,128.95 176.7,129.7 C149.2@176.75,129.75 ; C149.2@176.7,129.75 176.7,131.4 R228.1@176.75,131.45
NetC150_1: C150.1 C151.1 R227.1 R235.2 TP50.1 U15.22 | length 21.8
  Top Shielding/Sig w0.25: U15.22@172.25,126.9 172.25,128 172.658,128.408 172.658,129.457 C151.1@172.95,129.75
  Top Shielding/Sig w0.5: v1(165,128.25) 165.026,128.224 165.026,127.197 165.319,126.904 166.046,126.904 R235.2@166.2,126.75 ; C151.1@172.95,129.75 C150.1@172.95,131.5 172.975,131.525 172.975,133.425 R227.1@173,133.45 173.025,133.475 173.975,133.475 v1(174,133.5)
  PWR w0.5: v1(165,128.25) 165.005,128.255 165.005,128.755 167.75,131.5 172,131.5 v1(174,133.5)
NetC152_1: C152.1 R234.1 | length 1.8
  Top Shielding/Sig w0.25: R234.1@187.25,127.25 187.5,127 C152.1@187.5,125.55
NetC153_1: C153.1 Q22.3 R235.1 U15.1 | length 16.4
  Top Shielding/Sig w0.25: Q22.3@161.25,134.25 161.25,133.75 160.95,133.45 160.95,130.015 161.215,129.75 165,129.75 166,128.75 C153.1@166.75,128.75 167.5,128.75 167.75,128.5 167.75,127 R235.1@168,126.75 ; R235.1@168,126.675 168.825,126.675 169.25,126.25 U15.1@170.6,126.25
NetC154_2: C154.2 R238.1 U15.21 | length 11.6
  Top Shielding/Sig w0.25: v1@170.25,133.5 R238.1@171.2,133.5 ; C154.2@171.25,131.55 R238.1@171.25,133.45 R238.1@171.25,133.5 ; U15.21@172.75,126.75 172.75,127.5 v1(173.75,128.5)
  Sig 1 w0.25: v1(170.109,133.551) 170.183,133.478 170.183,133.067 173.75,129.5 v1(173.75,128.5)
NetC156_1: C156.1 TP54.1 U15.14 | length 2
  Top Shielding/Sig w0.25: U15.14@174.4,124.25 175.25,124.25 175.5,124 176.2,124 C156.1@176.25,124.05
NetC163_2: C163.2 C164.1 U16.28 | length 4.8
  Top Shielding/Sig w0.2: U16.28@61.062,63.4 61.062,65.862 C163.2@61.2,66
  Top Shielding/Sig w0.25: C163.2@61.2,66 61.2,67.75 C164.1@61.45,68
NetC171_1: C171.1 U16.32 | length 2.7
  Top Shielding/Sig w0.2: C171.1@58.25,65.725 58.25,65.125 59.062,64.313 U16.32@59.062,63.4
NetC171_2: C171.2 U16.33 | length 4.8
  Top Shielding/Sig w0.2: C171.2@58.25,67.425 57.5,66.675 57.5,65.187 58.562,64.125 U16.33@58.562,63.4
NetC172_2: C172.2 U16.34 | length 5
  Top Shielding/Sig w0.2: C172.2@56,67.275 56.158,67.117 56.633,67.117 57,66.75 57,65.066 58.062,64.004 U16.34@58.062,63.4
NetC173_2: C173.2 R263.2 | length 2
  Top Shielding/Sig w0.2: C173.2@52.125,67.505 54.045,67.505 R263.2@54.125,67.425
NetC179_2: C179.2 R269.2 | length 1.4
  Top Shielding/Sig w0.2: R269.2@50.3,58.5 C179.2@51.745,58.5
NetC181_2: C181.2 R274.2 | length 1.4
  Top Shielding/Sig w0.2: R274.2@50.3,56 C181.2@51.745,56
NetD1_1: D1.1 R1.1 | length 2.5
  Top Shielding/Sig w0.25: D1.1@153.5,8.25 R1.1@153.5,10.7
NetD2_1: D2.1 R2.1 | length 2.5
  Top Shielding/Sig w0.25: D2.1@176.5,8.25 R2.1@176.5,10.7
NetD3_2: D3.2 R3.1 | length 1.8
  Top Shielding/Sig w0.25: R3.1@156,36.55 156.2,36.75 D3.2@157.7,36.75
NetD4_1: D4.1 R15.1 | length 1.7
  Top Shielding/Sig w0.25: D4.1@82.5,8.75 R15.1@82.5,10.45
NetD5_1: D5.1 R16.1 | length 1.7
  Top Shielding/Sig w0.25: D5.1@57.5,8.75 R16.1@57.5,10.45
NetD7_1: D7.1 R30.1 | length 1.5
  Top Shielding/Sig w0.25: D7.1@17.5,91.5 R30.1@17.5,92.95
NetD8_2: D8.2 R33.1 R34.2 R38.1 | length 9.2
  Top Shielding/Sig w0.25: R34.2@53.734,102 54.244,101.49 54.244,101.256 55.625,99.875 56.68,99.875 57.012,99.543 D8.2@57.012,99.5 57.012,99.348 55.425,97.76 55.425,97.725 55.075,97.375 R38.1@55.05,97.375 R33.1@55.05,95.625
NetD9_2: D9.2 R39.1 | length 1.7
  Top Shielding/Sig w0.25: D9.2@42.5,119.75 D9.2@42.5,119.8 R39.1@42.5,121.4
NetD11_1: D11.1 R47.1 | length 1.7
  Top Shielding/Sig w0.5: D11.1@145,163.25 R47.1@145,164.95
NetD13_1: D13.1 R58.1 | length 1.9
  Top Shielding/Sig w0.25: D13.1@145.088,146.912 R58.1@145.088,148.713
  Top Shielding/Sig w0.5: R58.1@145.05,148.75 R58.1@145.088,148.713 ; D13.1@145.088,146.912 D13.1@145.125,146.875
NetD14_2: D14.2 R64.1 | length 1.9
  Top Shielding/Sig w0.25: D14.2@230,24.8 R64.1@230,26.7
NetD15_1: D15.1 R69.1 | length 2.2
  Top Shielding/Sig w0.25: D15.1@203.75,5.75 R69.1@203.75,7.95
NetD16_1: D16.1 R70.1 | length 2.2
  Top Shielding/Sig w0.25: D16.1@226.25,5.75 R70.1@226.25,7.95
NetD17_1: D17.1 R77.1 | length 1.4
  Top Shielding/Sig w0.25: D17.1@235.5,33.25 R77.1@235.5,34.7
NetD18_1: D18.1 R78.1 | length 1.4
  Top Shielding/Sig w0.25: 236.25,45.3 236.25,46.75
NetD19_2: D19.2 R104.1 | length 1.7
  Top Shielding/Sig w0.5: D19.2@190.75,39.55 190.775,39.575 190.775,41.225 R104.1@190.8,41.25
NetD20_1: D20.1 R105.1 | length 1.5
  Top Shielding/Sig w0.25: D20.1@200,17.5 200,16.05 R105.1@200.05,16
NetD21_1: D21.1 R106.1 | length 1.5
  Top Shielding/Sig w0.25: R106.1@190.95,16 191,16.05 D21.1@191,17.5
NetD22_1: D22.1 R107.1 | length 1.5
  Top Shielding/Sig w0.25: D22.1@189,17.5 189,16.05 R107.1@189.05,16
NetD23_1: D23.1 R108.1 | length 1.5
  Top Shielding/Sig w0.25: R108.1@179.95,16 179.95,17.45 D23.1@180,17.5
NetD24_2: D24.2 T1.1 | length 0.1
  Top Shielding/Sig w0.25: T1.1@234.425,80.075 T1.1@234.5,80
  other v2: 241,88.5 243.5,88.5
  other v3: 227.856,74.285 228.872,74.285 229.888,74.285 242.239,74.285 243.255,74.285 244.271,74.285 245.287,74.285 227.856,75.301 242.239,75.301 243.255,75.301 244.271,75.301 245.287,75.301 227.856,76.317 242.239,76.317 243.255,76.317 244.271,76.317 245.287,76.317 242.239,77.333 243.255,77.333 244.271,77.333 245.287,77.333 242.239,78.349 243.255,78.349 244.271,78.349 245.287,78.349 242.239,79.365 243.255,79.365 244.271,79.365 245.287,79.365 242.239,80.635 243.255,80.635 244.271,80.635 245.287,80.635 242.239,81.651 243.255,81.651 244.271,81.651 245.287,81.651 242.239,82.667 243.255,82.667 244.271,82.667 245.287,82.667 227.856,83.683 242.239,83.683 243.255,83.683 244.271,83.683 245.287,83.683 227.856,84.699 242.239,84.699 243.255,84.699 244.271,84.699 245.287,84.699 227.856,85.715 228.872,85.715 229.888,85.715 242.239,85.715 243.255,85.715 244.271,85.715 245.287,85.715
NetD25_2: D25.2 D26.2 | length 2.8
  Top Shielding/Sig w1: D26.2@227.17,112.5 D25.2@230,112.5
NetD27_1: D27.1 R116.1 | length 2.5
  Top Shielding/Sig w0.25: D27.1@180,88.25 182.45,88.25 R116.1@182.5,88.3
NetD28_2: D28.2 R136.1 | length 1.5
  Top Shielding/Sig w0.25: D28.2@23.5,30.05 23.5,31.45 R136.1@23.55,31.5
NetD29_1: D29.1 R139.1 | length 2
  Top Shielding/Sig w0.25: R139.1@35.45,6.25 35.45,4.3 D29.1@35.5,4.25
NetD30_1: D30.1 R140.1 | length 2
  Top Shielding/Sig w0.25: D30.1@52,4.25 52,6.2 R140.1@52.05,6.25
NetD31_1: D31.1 R150.1 | length 2.2
  Top Shielding/Sig w0.25: D31.1@13.75,6.5 R150.1@13.75,8.7
NetD35_1: D35.1 R161.1 | length 1.5
  Top Shielding/Sig w0.25: D35.1@125,177.75 R161.1@125,179.2
NetD36_1: D36.1 R191.2 | length 5.3
  Top Shielding/Sig w0.25: R191.2@51.2,140.5 51.454,140.754 51.454,141.204 51.95,141.7 53.435,141.7 54.848,143.113 D36.1@55,143.113 D36.1@54.887,143
NetD36_2: D36.2 R169.1 R170.1 R171.1 R173.1 R174.2 R182.1 TP16.1 | length 18.2
  Top Shielding/Sig w0.25: R182.1@57.5,145.55 R182.1@57.5,146 57.25,146.25 55.138,146.25 D36.2@55,146.388 55,147.7 R170.1@55,147.95 R173.1@57.5,147.95 R169.1@60,147.95 ; R174.2@60,146.016 R169.1@60,147.95 ; TP16.1@66.25,148.75 64.5,148.75 63.7,147.95 62.5,147.95 R169.1@60,147.95
NetD37_2: D37.2 R183.1 | length 1.8
  Top Shielding/Sig w0.25: R183.1@30.5,135 D37.2@30.5,136.75
NetD40_1: D40.1 R199.1 | length 2
  Top Shielding/Sig w0.25: R199.1@242.5,49.2 244.45,49.2 D40.1@244.5,49.25
NetD41_2: D41.2 R214.1 | length 1.8
  Top Shielding/Sig w0.25: D41.2@171.75,70.25 R214.1@171.75,72
NetD42_2: D42.2 R215.1 | length 1.8
  Top Shielding/Sig w0.25: R215.1@175,72 175.05,71.95 D42.2@175.05,70.25
NetD45_1: D45.1 R300.2 | length 2.8
  Top Shielding/Sig w0.25: R300.2@180.25,129.25 181.21,129.25 182.348,128.112 D45.1@182.5,128.112 D45.1@182.413,128.2
NetD45_2: D45.2 R230.1 R231.1 R232.1 R233.1 R234.2 R243.1 TP26.1 | length 18.7
  Top Shielding/Sig w0.25: D45.2@182.5,131.388 182.813,131.7 R233.1@185,131.7 ; R243.1@185,130.3 R233.1@185,131.7 ; R234.2@187.5,129.516 R230.1@187.5,131.7 ; TP26.1@197.5,131.75 192.55,131.75 192.5,131.7 190,131.7 R230.1@187.5,131.7 ; R233.1@185,131.7 R230.1@187.5,131.7
NetD46_2: D46.2 R244.1 | length 1.5
  Top Shielding/Sig w0.25: R244.1@170,115.5 D46.2@170,117
NetD47_1: D47.1 R253.1 | length 2.1
  Top Shielding/Sig w0.25: R253.1@33.55,74 R253.1@33.75,73.8
  Top Shielding/Sig w0.5: D47.1@33.75,72 R253.1@33.75,73.8
NetD48_1: D48.1 R254.1 | length 2.1
  Top Shielding/Sig w0.25: R254.1@33.55,56.5 R254.1@33.75,56.3
  Top Shielding/Sig w0.5: D48.1@33.75,54.5 R254.1@33.75,56.3
NetD49_1: D49.1 R255.1 | length 2.1
  Top Shielding/Sig w0.25: R255.1@33.55,39 R255.1@33.75,38.8
  Top Shielding/Sig w0.5: D49.1@33.75,37 R255.1@33.75,38.8
NetD50_2: D50.2 R267.1 | length 1.5
  Top Shielding/Sig w0.25: D50.2@62.4,69.75 62.5,69.85 R267.1@62.5,71.25
NetD51_1: D51.1 R182.2 | length 7.7
  Top Shielding/Sig w0.25: D51.1@55,138.112 55.863,138.112 57.5,139.75 R182.2@57.5,144.25
NetD51_2: D51.2 R191.1 U12.16 | length 16.2
  Top Shielding/Sig w0.25: U12.16@41.9,140.25 42.859,140.25 43.859,141.25 45.334,141.25 46.084,142 48.265,142 51.015,139.25 52.5,139.25 52.75,139.5 R191.1@52.75,140.5 ; R191.1@52.8,140.5 52.825,140.5 53.175,140.85 53.175,140.875 53.55,141.25 D51.2@54.75,141.25 ; D51.2@54.7,141.45 D51.2@54.75,141.5
NetD52_1: D52.1 R243.2 | length 2
  Top Shielding/Sig w0.25: D52.1@185,126.75 R243.2@185,128.7
NetD52_2: D52.2 R300.1 U15.16 | length 14
  Top Shielding/Sig w0.25: U15.16@174.4,125.25 175,125.25 175.281,125.531 175.281,125.922 175.709,126.35 176.85,126.35 177.893,127.393 180.143,127.393 R300.1@180.25,127.5 ; R300.1@180.313,127.562 180.25,127.625 R300.1@180.25,127.65 180.25,127.393 180.435,127.393 180.553,127.275 180.553,126.947 184,123.5 184.75,123.5 D52.2@185,123.25
NetD53_1: D53.1 R298.2 | length 2
  Top Shielding/Sig w0.25: R298.2@52.75,153.55 D53.1@52.75,155.5
NetD54_1: D54.1 R301.2 | length 5.5
  Top Shielding/Sig w0.25: D54.1@163,138.5 164,138.5 164.75,137.75 166.25,137.75 166.75,137.25 R301.2@166.75,136.1 R301.2@166.75,136
NetJ1_1: J1.1 R48.1 | length 19.5
  Top Shielding/Sig w0.25: v1@116.75,159.544 R48.1@116.75,161.2
  Sig 1 w0.25: J1.1@102.75,168.75 104.285,168.75 113.677,159.358 116.372,159.358 116.558,159.544 v1(116.663,159.544)
NetJ1_3: J1.3 R56.2 | length 2.8
  Top Shielding/Sig w0.25: R56.2@97.3,166 97.46,166.16 97.46,168.71 J1.3@97.5,168.75
NetJ2_1: J2.1 R57.1 | length 6.5
  Top Shielding/Sig w0.25: J2.1@104.25,145.75 105.25,145.75 106,145 107.75,143.25 R57.1@109.75,143.25
NetJ2_2: J2.2 U5.5 | length 32.1
  Top Shielding/Sig w0.25: v1@127.25,143.25 127.25,143.267 v1(129,145.018) ; v1(133.25,145.018) 133.324,144.944 133.324,144.421 133.745,144 U5.5@134.237,144
  Sig 1 w0.25: J2.2@104.25,143.5 104.453,143.297 105.45,143.297 106.247,142.5 126.429,142.5 v1(127.131,143.203) ; v1@129,145 129.018,145.018 v1(133.25,145.018)
NetJ2_3: J2.3 R62.2 | length 5.7
  Top Shielding/Sig w0.25: J2.3@104.25,140.92 107.42,140.92 107.8,141.3 R62.2@109.75,141.3
NetJ3_1: J3.1 R138.1 | length 47
  Top Shielding/Sig w0.25: v2@44.5,25.75 44.75,26 R138.1@44.75,26.95
  Sig 1 w0.25: J3.1@10.25,18.25 11,18.25 15,14.25 v1(35.25,14.25) ; v1(35.835,23.5) 35.862,23.527 36.527,23.527 38.45,25.45 43.084,25.45 43.304,25.67 v2(44.471,25.67)
  Sig 4 w0.25: v1(35.25,14.25) 35.25,22.915 v1(35.835,23.5)
NetJ3_3: J3.3 R141.2 | length 54.4
  Top Shielding/Sig w0.25: v2(42.75,26.075) 42.75,26.133 43,26.383 R141.2@43,27.2
  Sig 1 w0.25: J3.3@5.25,18.25 6,18.25 6.25,18 6.25,17 6.75,16.5 10,16.5 11.75,14.75 11.75,13.25 12.75,12.25 33.75,12.25 v1(34.25,12.75) ; v1(35,23.75) 37.325,26.075 v2(42.75,26.075)
  Sig 4 w0.25: v1(34.25,12.75) 34.25,23 v1(35,23.75)
NetJ4_1: J4.1 R149.1 | length 18.9
  Top Shielding/Sig w0.25: v1(25,29.75) R149.1@26.2,29.75
  Sig 1 w0.25: J4.1@10,23.25 15.5,28.75 24,28.75 v1(25,29.75)
NetJ4_3: J4.3 R152.2 | length 25
  Top Shielding/Sig w0.25: v1(25.018,31.5) R152.2@26.2,31.5
  Sig 1 w0.25: J4.3@4.75,23 9.25,27.5 12.25,27.5 14.25,29.5 23,29.5 25,31.5 v1(25.018,31.5)
NetJ13_10: J13.10 S1.2 | length 122.2
  Top Shielding/Sig w0.25: S1.2@10.15,31 11.846,31 12.171,31.324 v1(12.171,31.329)
  Sig 1 w0.25: v1(12.171,31.329) 12.171,32.171 12.25,32.25 15,35 31.25,35 36.25,40 40,40 42.5,42.5 v1(95.25,42.5)
  Sig 4 w0.25: v1(95.25,42.5) J13.10@95.25,74.295
NetJ15_56: J15.56 S2.1 | length 167.6
  Top Shielding/Sig w0.25: S2.1@10.15,26.75 12.679,26.75 14.009,25.421 v1(14.079,25.421)
  Sig 1 w0.25: v1@14,25.5 14,16.25 14.887,15.363 49.637,15.363 58.5,6.5 105.25,6.5 107.995,9.245 144.745,9.245 v2(144.75,9.25) ; J15.56@141,23.5 144.25,23.5 v1(145,22.75)
  Sig 4 w0.25: v2(144.75,9.25) 144.75,9.321 145,9.571 v1(145,22.75)
NetJ19_1: J19.1 R134.1 | length 41.9
  Top Shielding/Sig w0.25: J19.1@10,14 J19.1@10.04,13.96 ; v2(36,25.75) 36.095,25.75 36.483,26.138 36.743,26.138 36.755,26.15 R134.1@37.75,26.15
  Sig 1 w0.25: J19.1@10.04,14 12.666,11.374 33.376,11.374 v1@33.5,11.25
  Sig 4 w0.25: v1@33.5,11.5 33.5,23.25 v2(36,25.75)
  other v1: 33.535,11.374
NetJ19_3: J19.3 R304.2 | length 3.5
  Top Shielding/Sig w0.25: R304.2@4.9,10.5 4.96,10.56 4.96,13.96 J19.3@5,14
NetJ20_1: J20.1 U13.6 | length 12
  Top Shielding/Sig w0.25: J20.1@27.5,128 29.25,128 29.75,127.5 29.75,122.75 31.25,121.25 32.854,121.25 33,121.396 U13.6@33,122.3
NetJ20_2: J20.2 U13.7 | length 10.8
  Top Shielding/Sig w0.25: J20.2@27.5,125.5 28.75,125.5 29.3,124.95 29.3,122.45 31,120.75 33.25,120.75 33.5,121 U13.7@33.5,122.3
NetJ20_3: J20.3 U13.8 | length 10
  Top Shielding/Sig w0.25: J20.3@27.75,123 27.846,122.904 28.7,122.904 28.85,122.754 28.85,121.65 30.25,120.25 33.854,120.25 34,120.396 U13.8@34,122.3
NetJ20_4: J20.4 U13.9 | length 9.7
  Top Shielding/Sig w0.25: J20.4@27.5,120.44 27.61,120.44 28.3,119.75 34.25,119.75 34.5,120 U13.9@34.5,122.3
NetQ1_1: Q1.1 R24.2 | length 9.2
  Top Shielding/Sig w0.25: Q1.1@40.5,96.57 40.57,96.5 v1(41.75,96.5) ; v1(41.75,103.5) R24.2@42.7,103.5
  Sig 4 w0.25: v1(41.75,96.5) v1(41.75,103.5)
NetQ2_1: Q2.1 R33.2 TP5.1 | length 14.1
  Top Shielding/Sig w0.25: Q2.1@50.5,96.5 v1(51.75,96.5) 51.75,95.875 52,95.625 R33.2@53.45,95.625
  Sig 1 w0.25: v1(51.75,96.5) 59,96.5 TP5.1@61.25,98.75
NetQ3_4: Q3.4 R115.2 | length 20.4
  Top Shielding/Sig w0.25: R115.2@218.75,90.8 v1(218.75,92) ; Q3.4@221.137,108.405 221.25,108.518 v1(221.25,109.25)
  Sig 4 w0.25: v1(218.75,92) 218.75,100.25 220,101.5 220,108 v1(221.25,109.25)
NetQ4_4: Q4.4 Q6.4 R113.1 R117.2 TP11.1 | length 41.9
  Top Shielding/Sig w0.25: v1(193.75,110.5) R113.1@193.75,111.7 ; v1(198.75,84.5) R117.2@202.95,84.5 ; v1(198.75,95.75) 198.75,96.482 Q6.4@198.863,96.595 ; v1(198.75,103.75) 198.75,104.482 Q4.4@198.863,104.595
  Sig 1 w0.25: TP11.1@188.75,111.25 193,111.25 v1(193.75,110.5)
  Sig 4 w0.25: v1(193.75,110.5) 193.75,106.5 196.5,103.75 v1(198.75,103.75) v1(198.75,95.75) v1(198.75,84.5)
NetQ5_4: Q5.4 R114.2 | length 11.3
  Top Shielding/Sig w0.25: Q5.4@221.137,100.405 221.25,100.518 v1(221.25,101.25) ; R114.2@221.25,90.8 v1(221.25,92)
  Sig 4 w0.25: v1(221.25,92) v1(221.25,101.25)
NetQ7_1: Q7.1 R157.2 | length 69.1
  Top Shielding/Sig w0.25: R157.2@48.05,135.25 v1(49.5,135.25) ; Q7.1@69.25,180.25 69.25,181.658 69.5,181.908 v2@69.5,182
  Sig 1 w0.25: v1(49.5,135.25) 66.25,135.25 v1(67,136)
  Sig 4 w0.25: v1(67,136) 67,144.75 70.75,148.5 70.75,180.75 v2@69.533,181.967
  other v2: 69.436,181.938
NetQ9_1: Q9.1 R171.2 | length 25.7
  Top Shielding/Sig w0.25: R171.2@62.5,149.5 v1(62.5,150.75) ; Q9.1@65.5,171.57 65.57,171.5 v1(66.75,171.5)
  Sig 4 w0.25: v1(62.5,150.75) 67.5,155.75 67.5,170.75 v1(66.75,171.5)
NetQ10_1: Q10.1 R169.2 | length 31.6
  Top Shielding/Sig w0.25: v1(56.25,178.5) 57.43,178.5 Q10.1@57.5,178.43 ; R169.2@60,149.75 v1(60,150.75)
  Sig 4 w0.25: v1(56.25,178.5) 56.25,161.25 60,157.5 v1(60,150.75)
NetQ11_1: Q11.1 R170.2 | length 27.7
  Top Shielding/Sig w0.25: Q11.1@48.25,171.5 48.5,171.75 v1(49,171.75) ; R170.2@55,149.55 v1(55,150.75)
  Sig 1 w0.25: v1@49.5,156.75 50.25,156 54,156 55,155 v6(55,154)
  Sig 4 w0.25: v1(49,171.75) 49,171.646 49.463,171.183 v1(49.463,156.724) ; v1(55,150.75) v6(55,154)
NetQ12_1: Q12.1 R173.2 | length 48.8
  Top Shielding/Sig w0.25: v1@38.75,178.5 38.82,178.43 Q12.1@40,178.43 ; R173.2@57.5,149.55 v1(57.5,150.75)
  Sig 1 w0.25: v2(38.5,156.75) 39.25,157.5 53.5,157.5 56.75,154.25 v6(57.5,154.25)
  Sig 4 w0.25: v2(38.5,156.75) 38,157.25 38,177.662 38.673,178.335 v1(38.673,178.439) ; v1(57.5,150.75) v6(57.5,154.25)
NetQ13_2: Q13.2 R175.1 | length 1.6
  Top Shielding/Sig w0.25: Q13.2@32.45,149.9 Q13.2@32.5,149.95 ; Q13.2@32.5,150 32.46,150 32.45,150.01 32.45,151.45 R175.1@32.5,151.5
NetQ14_4: Q14.4 R193.2 | length 29.8
  Top Shielding/Sig w0.25: R193.2@181.25,56.7 181.3,56.75 v1(182.642,56.75) ; v1(202.75,68.25) 202.75,67.436 Q14.4@202.781,67.405
  Sig 1 w0.25: v1(182.642,56.75) 182.636,56.756 182.636,58.859 182.5,58.995 182.5,61 189.75,68.25 v1(202.75,68.25)
NetQ15_4: Q15.4 R202.2 TP21.1 | length 29.4
  Top Shielding/Sig w0.25: R202.2@198.3,53 v1(200,53) ; v1(202.75,60.25) 202.75,59.436 Q15.4@202.781,59.405
  Sig 4 w0.25: TP21.1@198.75,73.75 201.25,73.75 205,70 205,68.25 202.75,66 v1(202.75,60.25) 202.75,55.75 v1(200,53)
NetQ16_1: Q16.1 Q16.3 R209.2 U14.10 | length 5.8
  Top Shielding/Sig w0.25: Q16.1@174,56.6 174,57.35 174.5,57.85 Q16.3@174.5,57.9 176.35,57.9 R209.2@176.5,58.05 176.55,58.1 U14.10@176.55,60.25
NetQ17_1: Q17.1 R219.2 | length 52.2
  Top Shielding/Sig w0.25: Q17.1@180.5,173 180.604,172.896 180.604,172.396 v1(181.25,171.75) ; R219.2@181.55,123.25 v1(183,123.25)
  Sig 4 w0.25: v1(181.25,171.75) 181.25,131.25 183,129.5 v1(183,123.25)
NetQ18_1: Q18.1 R230.2 | length 42.9
  Top Shielding/Sig w0.25: R230.2@187.5,133.55 v1(187.5,135) ; Q18.1@192.5,171.57 192.57,171.5 v1(193.75,171.5)
  Sig 4 w0.25: v1(187.5,135) 187.5,140 193.916,146.416 193.916,161.416 195,162.5 195,170.25 v1(193.75,171.5)
NetQ19_1: Q19.1 R233.2 | length 47.2
  Top Shielding/Sig w0.25: v1(183.25,178.5) 184.43,178.5 Q19.1@184.5,178.43 ; R233.2@185,133.55 v1@185,135.25
  Sig 4 w0.25: v1(183.25,178.5) 183.25,136.75 v1(185,135)
NetQ20_1: Q20.1 R231.2 | length 55.6
  Top Shielding/Sig w0.25: R231.2@192.5,133.55 v1@192.5,135.25 ; Q20.1@210,171.57 210.07,171.5 v1(211.25,171.5)
  Sig 4 w0.25: v1(192.5,135) 205,135 212.5,142.5 212.5,170.25 v1(211.25,171.5)
NetQ21_1: Q21.1 R232.2 | length 50.7
  Top Shielding/Sig w0.25: R232.2@190,133.55 v1(190,135) ; v1(200.75,178.5) 201.93,178.5 Q21.1@202,178.43
  Sig 4 w0.25: v1(190,135) 190,140 195,145 195,160 197.5,162.5 197.5,172.5 200.75,175.75 v1(200.75,178.5)
NetQ22_2: Q22.2 R236.1 | length 1.4
  Top Shielding/Sig w0.25: Q22.2@160.6,135.95 Q22.2@160.6,136.2 R236.1@160.6,137.35
NetR7_2: R7.2 U1.15 | length 1.9
  Top Shielding/Sig w0.2: R7.2@164.5,33.17 164.5,33.15 164.75,32.9 U1.15@164.75,31.375
NetR9_2: R9.2 U1.13 | length 2
  Top Shielding/Sig w0.2: U1.13@165.75,31.375 165.75,32.125 166.25,32.625 R9.2@166.25,33.17
NetR10_2: R10.2 U1.14 | length 1.9
  Top Shielding/Sig w0.2: U1.14@165.25,31.375 165.25,32.9 165.5,33.15 R10.2@165.5,33.17
NetR11_2: R11.2 U1.16 | length 2
  Top Shielding/Sig w0.2: R11.2@163.75,33.17 163.75,32.625 164.25,32.125 U1.16@164.25,31.375
NetR13_2: R13.2 U2.13 | length 1.4
  Top Shielding/Sig w0.25: R13.2@69.75,33.17 69.835,33.085 69.835,32.74 70,32.575 U2.13@70,31.875
NetR17_2: R17.2 U2.14 | length 1.6
  Top Shielding/Sig w0.25: R17.2@69,33.25 69.085,33.165 69.085,32.729 69.5,32.314 U2.14@69.5,31.875
NetR19_2: R19.2 U2.15 | length 1.6
  Top Shielding/Sig w0.25: R19.2@68.25,33.17 68.25,32.75 68.5,32.5 69,32 U2.15@69,31.875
